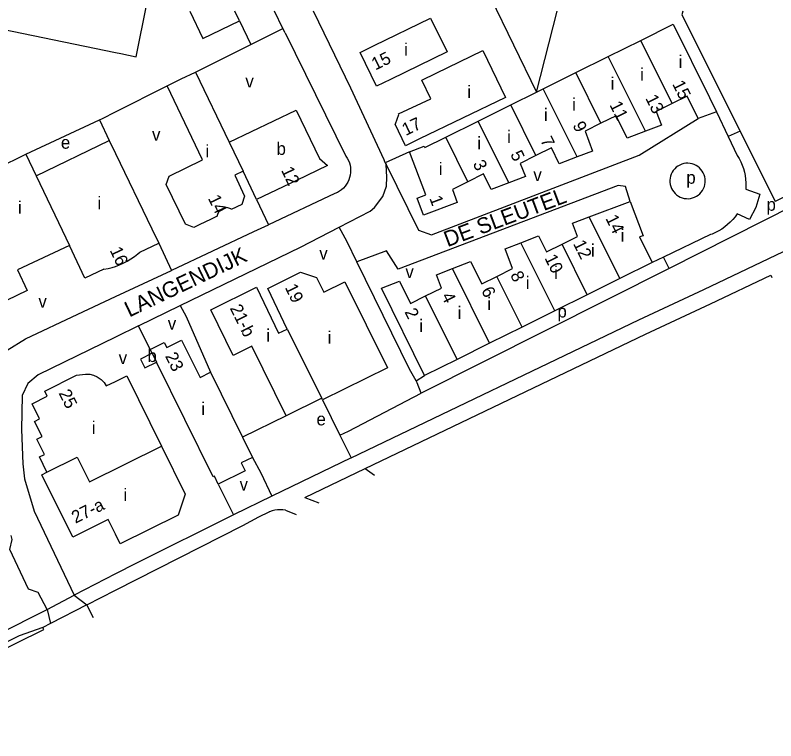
# Model space of a CAD drawing. Extents: x 157699 to 159683, y 381451 to 383293.
# Drawn here: x 158018.2 to 158260, y 381518.2 to 381748.7 of the extents above; entities that cross this region are included whole.
import ezdxf

# ---------------------------------------------------------------- set-up
doc = ezdxf.new("R2010")
doc.units = 0
for name, color, linetype in [('BLT_Basislijn', 7, 'Continuous'), ('BLT_Bebouwing', 7, 'Continuous'), ('BLT_Centroide', 7, 'Continuous'), ('BLT_Huisnummer', 7, 'Continuous'), ('BLT_Huisnummer_ tussenligend', 7, 'Continuous'), ('BLT_Huisnummer_reeks', 7, 'Continuous'), ('BLT_Onderverdeling_panden', 7, 'Continuous'), ('BLT_Straatnaam', 7, 'Continuous')]:
    doc.layers.add(name, color=color, linetype=linetype)

msp = doc.modelspace()

# ---------------------------------------------------------------- linework, layer by layer
at = {"layer": 'BLT_Basislijn'}
for p, q in [((158167.81, 381757.42), (158183.84, 381724.24)), ((158103.23, 381744.54), (158100.56, 381750)), ((158183.84, 381724.24), (158190.41, 381750)), ((158089.49, 381746.92), (158093.05, 381739.46)), ((158093.05, 381739.46), (158103.23, 381744.54)), ((158103.94, 381743.1), (158103.23, 381744.54)), ((158103.94, 381743.1), (158123.3, 381703.95)), ((158075.43, 381730.66), (158093.05, 381739.46)), ((158050, 381717.98), (158066.42, 381726.3)), ((158241.14, 381718.07), (158244.87, 381710.14)), ((158021.49, 381704.53), (158044.98, 381715.47)), ((158044.98, 381715.47), (158048.02, 381708.92)), ((158315.83, 381713.68), (158226.02, 381668.19)), ((158248.59, 381711.93), (158244.87, 381710.14)), ((158244.87, 381710.14), (158247.68, 381704.16)), ((158143.48, 381705.35), (158135.8, 381701.79)), ((158135.8, 381701.79), (158136.06, 381701.27)), ((158119.78, 381692.03), (158098.65, 381682.14)), ((158094.92, 381690.12), (158098.65, 381682.14)), ((158239.16, 381678.99), (158224.27, 381671.88)), ((158063.79, 381676.31), (158067.82, 381667.64)), ((158224.27, 381671.88), (158220.69, 381670.15)), ((158226.02, 381668.19), (158224.27, 381671.88)), ((158050, 381659.32), (158067.82, 381667.64)), ((158226.02, 381668.19), (158147.23, 381628.64)), ((158239.25, 381657.03), (158258.38, 381666.16)), ((158258.38, 381666.16), (158258.75, 381665.39)), ((158057.32, 381650.02), (158070.61, 381656.49)), ((158057.32, 381650.02), (158050, 381646.44)), ((158061.07, 381642.53), (158057.32, 381650.02)), ((158145.59, 381632.5), (158148.31, 381634.22)), ((158115.88, 381626.52), (158121.4, 381615.3)), ((158104.27, 381621.43), (158090.45, 381614.62)), ((158121.4, 381615.3), (158124.96, 381608.09)), ((158093.61, 381608.23), (158096.23, 381603.34)), ((158124.96, 381608.09), (158099.76, 381595.91)), ((158110.21, 381595.49), (158129.38, 381604.66)), ((158096.23, 381603.34), (158099.76, 381595.91)), ((158082.69, 381599.75), (158087.61, 381589.91)), ((158099.76, 381595.91), (158087.61, 381589.91)), ((158110.21, 381595.49), (158114.68, 381593.72)), ((158095.57, 381589.28), (158098.89, 381590.86)), ((158050, 381571.17), (158036.94, 381564.44)), ((158040.88, 381561.38), (158050, 381566.01)), ((158028.36, 381559.84), (158036.94, 381564.44)), ((158036.94, 381564.44), (158040.88, 381561.38)), ((157952.35, 381521.92), (158028.36, 381559.84)), ((158028.36, 381559.84), (158029.42, 381555.45))]:
    msp.add_line(p, q, dxfattribs=at)
for points in [[(158135.8, 381701.79), (158135.43, 381702.75), (158124.84, 381725.53), (158113.04, 381750)], [(158044.98, 381715.47), (158045.91, 381715.91), (158050, 381717.98)], [(158136.06, 381701.27), (158146.36, 381680.4), (158150.5, 381678.91), (158216.51, 381704.23), (158235.32, 381715.92)], [(158237.13, 381661.56), (158335.95, 381708.7)], [(158123.3, 381703.95), (158123.73, 381703.29), (158124.1, 381702.58), (158124.39, 381701.85), (158124.6, 381701.08), (158124.74, 381700.3), (158124.79, 381699.51), (158124.77, 381698.72), (158124.67, 381697.93), (158124.49, 381697.16), (158124.23, 381696.42), (158123.89, 381695.7), (158123.49, 381695.02), (158123.02, 381694.38), (158122.49, 381693.79), (158121.9, 381693.26), (158121.26, 381692.79), (158120.58, 381692.39), (158119.78, 381692.03)], [(158247.68, 381704.16), (158248.28, 381703.17), (158248.82, 381702.15), (158249.28, 381701.08), (158249.67, 381699.99), (158249.99, 381698.87), (158250.22, 381697.74), (158250.38, 381696.59), (158250.46, 381695.43), (158250.45, 381694.27), (158250.4, 381693.45)], [(158121.11, 381681.34), (158131.01, 381686.47), (158132.34, 381687.59), (158135.05, 381691.09), (158136.16, 381694.43), (158136.29, 381697.29), (158136.06, 381701.27)], [(158237.55, 381696.05), (158237.51, 381696.72), (158237.39, 381697.38), (158237.19, 381698.02), (158236.92, 381698.64), (158236.58, 381699.22), (158236.17, 381699.75), (158235.7, 381700.23), (158235.18, 381700.65), (158234.61, 381701), (158234, 381701.29), (158233.36, 381701.5), (158232.71, 381701.63), (158232.04, 381701.69), (158231.37, 381701.66), (158230.7, 381701.56), (158230.06, 381701.38), (158229.44, 381701.12), (158228.85, 381700.79), (158228.31, 381700.39), (158227.82, 381699.93), (158227.39, 381699.42), (158227.02, 381698.86), (158226.72, 381698.26), (158226.5, 381697.62), (158226.35, 381696.97), (158226.28, 381696.3), (158226.29, 381695.63), (158226.38, 381694.96), (158226.55, 381694.31), (158226.79, 381693.69), (158227.11, 381693.1), (158227.5, 381692.55), (158227.94, 381692.05), (158228.45, 381691.6), (158229, 381691.22), (158229.6, 381690.91), (158230.22, 381690.67), (158230.87, 381690.51), (158231.54, 381690.43), (158232.21, 381690.42), (158232.88, 381690.5), (158233.53, 381690.65), (158234.16, 381690.88), (158234.76, 381691.19), (158235.32, 381691.56), (158235.83, 381692), (158236.28, 381692.49), (158236.68, 381693.04), (158237, 381693.62), (158237.25, 381694.25), (158237.43, 381694.89), (158237.53, 381695.56), (158237.55, 381696.05)], [(158213.69, 381689.55), (158212.21, 381694.3), (158209.89, 381694.63), (158139.91, 381667.98), (158136.2, 381673.83), (158126.8, 381670.38)], [(158250.4, 381693.45), (158254.87, 381691.85), (158253.61, 381687.61), (158251.62, 381683.78), (158247.7, 381685.65)], [(158247.7, 381685.65), (158247.03, 381684.7), (158246.3, 381683.81), (158245.51, 381682.96), (158244.65, 381682.17), (158243.75, 381681.44), (158242.8, 381680.78), (158241.81, 381680.18), (158240.77, 381679.65), (158239.71, 381679.2), (158239.16, 381678.99)], [(158067.82, 381667.64), (158068, 381667.72), (158093.98, 381679.96), (158098.65, 381682.14)], [(158070.61, 381656.49), (158108.83, 381675.05), (158121.11, 381681.34)], [(158126.8, 381670.38), (158123.71, 381676.69), (158121.11, 381681.34)], [(158145.59, 381632.5), (158143.51, 381636.23), (158126.8, 381670.38)], [(158124.96, 381608.09), (158216.4, 381651.88), (158237.13, 381661.56)], [(158008.63, 381627.66), (158009.36, 381632.35), (158010.31, 381635.34), (158013.56, 381640.27), (158015.56, 381642.29), (158021.48, 381645.93), (158038.06, 381653.74), (158050, 381659.32)], [(158070.61, 381656.49), (158072.54, 381652.96), (158080.25, 381635.26)], [(158129.38, 381604.66), (158218.54, 381647.36), (158239.25, 381657.03)], [(158050, 381646.44), (158025.46, 381634.4), (158022.15, 381631.68), (158020.34, 381627.92), (158020.13, 381617.1), (158020.61, 381606.15), (158021.13, 381601.42), (158024.19, 381591.16), (158036.94, 381564.44)], [(158147.23, 381628.64), (158145.9, 381631.95), (158145.59, 381632.5)], [(158121.4, 381615.3), (158124.07, 381616.56), (158147.23, 381628.64)], [(158129.38, 381604.66), (158132.38, 381602.52)], [(158087.61, 381589.91), (158056.49, 381574.51), (158050, 381571.17)], [(158104.14, 381591.43), (158103.28, 381591.55), (158102.41, 381591.58), (158101.54, 381591.53), (158100.68, 381591.4), (158099.84, 381591.19), (158099.02, 381590.91), (158098.89, 381590.86)], [(158104.14, 381591.43), (158107.51, 381590.1)], [(158050, 381566.01), (158090.55, 381586.59), (158095.57, 381589.28)], [(158028.36, 381559.84), (158025.47, 381565.25), (158022.36, 381566.33), (158016.43, 381578.93), (158017.17, 381582.14), (158016.92, 381583.37)], [(158040.88, 381561.38), (158029.42, 381555.45)], [(158043.09, 381557.25), (158040.88, 381561.38)], [(158026.95, 381554.17), (158019.39, 381551.51), (157952.98, 381518.16)], [(158011.15, 381542.3), (158009.99, 381545.03), (158027.25, 381553.57), (158026.95, 381554.17)], [(158029.42, 381555.45), (158026.95, 381554.17)]]:
    msp.add_lwpolyline(points, dxfattribs=at)
at = {"layer": 'BLT_Bebouwing'}
for p, q in [((158206.71, 381735.6), (158217.04, 381740.73)), ((158196.38, 381730.47), (158206.71, 381735.6)), ((158075.43, 381730.66), (158086.15, 381708.38)), ((158186.04, 381725.34), (158196.38, 381730.47)), ((158077.72, 381702.79), (158066.42, 381726.3)), ((158183.84, 381724.24), (158186.04, 381725.34)), ((158175.71, 381720.21), (158183.84, 381724.24)), ((158165.38, 381715.07), (158175.71, 381720.21)), ((158241.14, 381718.07), (158235.32, 381715.92)), ((158155.05, 381709.94), (158165.38, 381715.07)), ((158024.77, 381697.68), (158048.02, 381708.92)), ((158048.02, 381708.92), (158050, 381704.83)), ((158002.5, 381695.32), (158021.49, 381704.53)), ((158021.49, 381704.53), (158024.77, 381697.68)), ((158090.59, 381699.15), (158087.96, 381697.89)), ((158094.92, 381690.12), (158090.59, 381699.15)), ((158200.63, 381684.61), (158213.69, 381689.55)), ((158057.76, 381673.42), (158063.79, 381676.31)), ((158220.69, 381670.15), (158210.35, 381665.02)), ((158210.35, 381665.02), (158200.01, 381659.89)), ((158200.01, 381659.89), (158189.67, 381654.75)), ((158189.67, 381654.75), (158179.33, 381649.62)), ((158179.33, 381649.62), (158168.99, 381644.49)), ((158168.99, 381644.49), (158158.65, 381639.35)), ((158158.65, 381639.35), (158148.31, 381634.22)), ((158080.25, 381635.26), (158090.45, 381614.62)), ((158090.45, 381614.62), (158093.61, 381608.23))]:
    msp.add_line(p, q, dxfattribs=at)
for points in [[(158050, 381736.86), (158051.69, 381736.51), (158056.59, 381735.5), (158060.04, 381752.38)], [(158008.27, 381750), (158007.37, 381745.62), (158050, 381736.86)], [(158073.63, 381750), (158077.8, 381741.31), (158089.49, 381746.92)], [(158089.49, 381746.92), (158088.01, 381750)], [(158230.44, 381750), (158230.14, 381748.88), (158248.59, 381711.93)], [(158155.45, 381737.08), (158137.48, 381728.32), (158132.98, 381726.13), (158127.8, 381736.93), (158132.3, 381739.12), (158150.22, 381747.84), (158155.45, 381737.08)], [(158217.04, 381740.73), (158227.36, 381745.86), (158238.88, 381722.63), (158241.14, 381718.07)], [(158151.95, 381730.3), (158166.88, 381737.5), (158174.05, 381722.62), (158146.72, 381709.45), (158142.19, 381707.27), (158138.91, 381714.09), (158139.08, 381714.18), (158140.12, 381717.15), (158140.03, 381717.35), (158150.29, 381722.17), (158147.45, 381728.13), (158151.95, 381730.3)], [(158066.42, 381726.3), (158070.93, 381728.48), (158075.43, 381730.66)], [(158235.32, 381715.92), (158231.82, 381722.99), (158227.03, 381720.62)], [(158227.03, 381720.62), (158221.96, 381718.11), (158223.61, 381713.82), (158218.5, 381711.86)], [(158086.15, 381708.38), (158107.5, 381718.59), (158114.94, 381703.21), (158117.43, 381700.92), (158107.55, 381696.18), (158094.92, 381690.12)], [(158218.5, 381711.86), (158212.73, 381709.67), (158209.2, 381716.77), (158204.37, 381714.37)], [(158314.09, 381716.71), (158259.76, 381689.57)], [(158204.37, 381714.37), (158199.31, 381711.86), (158201.72, 381705.56), (158196.8, 381703.69)], [(158248.59, 381711.93), (158259.76, 381689.57)], [(158143.48, 381705.35), (158148.16, 381707.11), (158148.39, 381706.64), (158155.05, 381709.94)], [(158196.8, 381703.69), (158191.07, 381701.51), (158188.63, 381706.54), (158183.71, 381704.1)], [(158050, 381704.83), (158061.62, 381680.81), (158063.79, 381676.31)], [(158162.1, 381695.83), (158157.15, 381693.36), (158158.7, 381689.25), (158147.96, 381685.18), (158145.92, 381690.57), (158148.71, 381691.63), (158143.48, 381705.35)], [(158183.71, 381704.1), (158178.73, 381701.64), (158180.35, 381697.47), (158175.12, 381695.47)], [(158087.96, 381697.89), (158091.1, 381691.27), (158090.17, 381688.61), (158086.82, 381687.02), (158086.72, 381687.2), (158085.45, 381687.64), (158082.78, 381686.29), (158082.32, 381685.05), (158082.39, 381684.9), (158080.47, 381683.95), (158076.61, 381682.11), (158074.97, 381681.31), (158072.26, 381682.33), (158066.2, 381694.95), (158067.14, 381697.61), (158077.72, 381702.79)], [(158175.12, 381695.47), (158169.51, 381693.32), (158167.05, 381698.3), (158162.1, 381695.83)], [(158213.69, 381689.55), (158217.81, 381678.65), (158216.65, 381678.29), (158220.69, 381670.15)], [(158192.02, 381675.99), (158196.9, 381678.41), (158195.3, 381682.6), (158200.63, 381684.61)], [(158178.91, 381676.42), (158184.56, 381678.57), (158187.06, 381673.53), (158192.02, 381675.99)], [(158035.42, 381675.59), (158018.85, 381667.83), (158021.94, 381661.24), (158008.55, 381654.76), (158005.46, 381661.15), (158004.2, 381660.58)], [(158046.34, 381667.99), (158040.31, 381665.16), (158035.42, 381675.59)], [(158171.33, 381665.73), (158176.31, 381668.2), (158173.91, 381674.52), (158178.91, 381676.42)], [(158050, 381668.92), (158051.27, 381669.4), (158052.52, 381669.95), (158053.73, 381670.58), (158054.9, 381671.28), (158056.03, 381672.04), (158057.11, 381672.87), (158057.76, 381673.42)], [(158157.2, 381668.23), (158162.95, 381670.42), (158166.47, 381663.32), (158171.33, 381665.73)], [(158046.34, 381667.99), (158047.68, 381668.25), (158049, 381668.6), (158050, 381668.92)], [(158148.65, 381659.5), (158153.69, 381662), (158152.07, 381666.27), (158157.2, 381668.23)], [(158104.65, 381649), (158098.44, 381661.87), (158108.91, 381667.11), (158113.95, 381665.33), (158116.3, 381660.71), (158123, 381664.03), (158136.52, 381636.69), (158115.88, 381626.52)], [(158148.31, 381634.22), (158134.57, 381661.98), (158140.31, 381664.26), (158143.85, 381657.12), (158148.65, 381659.5)], [(158104.27, 381621.43), (158093.39, 381643.51), (158087.49, 381640.61), (158080.35, 381655.06), (158094.86, 381662.26), (158101.9, 381647.68), (158104.65, 381649)], [(158061.07, 381642.53), (158065.51, 381644.72), (158066.32, 381643.1), (158071.05, 381645.45), (158076.91, 381633.62), (158080.25, 381635.26)], [(158061.69, 381641.28), (158057.99, 381639.46), (158059.37, 381636.67), (158063.04, 381638.49)], [(158061.69, 381641.28), (158061.07, 381642.53)], [(158082.69, 381599.75), (158081.47, 381602.22), (158081.08, 381602.03), (158063.04, 381638.49)], [(158028.25, 381603.51), (158025.86, 381608.35), (158027.47, 381609.15), (158025.07, 381614), (158026.68, 381614.8), (158024.28, 381619.64), (158025.9, 381620.44), (158023.5, 381625.27), (158028.34, 381627.67), (158027.54, 381629.28), (158037.69, 381634.3), (158040.53, 381634.66), (158041.93, 381634.62), (158043.09, 381634.32), (158044.24, 381633.84), (158045.46, 381633), (158046.39, 381631.99), (158047.05, 381630.9)], [(158050, 381632.36), (158053.62, 381634.15), (158064.67, 381611.77)], [(158047.05, 381630.9), (158050, 381632.36)], [(158115.62, 381627.03), (158104.27, 381621.43)], [(158115.88, 381626.52), (158115.62, 381627.03)], [(158064.67, 381611.77), (158072.18, 381596.56), (158069.93, 381589.9), (158051.49, 381580.76), (158050, 381583.77)], [(158093.61, 381608.23), (158090.03, 381606.46), (158091.23, 381603.97), (158082.69, 381599.75)], [(158050, 381583.77), (158047.67, 381588.48), (158036.47, 381582.88), (158026.64, 381602.71), (158028.25, 381603.51)]]:
    msp.add_lwpolyline(points, dxfattribs=at)
at = {"layer": 'BLT_Onderverdeling_panden'}
for p, q in [((158227.03, 381720.62), (158217.04, 381740.73)), ((158218.5, 381711.86), (158206.71, 381735.6)), ((158204.37, 381714.37), (158196.38, 381730.47)), ((158196.8, 381703.69), (158186.04, 381725.34)), ((158183.71, 381704.1), (158175.71, 381720.21)), ((158175.12, 381695.47), (158165.38, 381715.07)), ((158086.15, 381708.38), (158090.59, 381699.15)), ((158162.1, 381695.83), (158155.05, 381709.94)), ((158024.77, 381697.68), (158035.42, 381675.59)), ((158210.35, 381665.02), (158200.63, 381684.61)), ((158189.67, 381654.75), (158178.91, 381676.42)), ((158200.01, 381659.89), (158192.02, 381675.99)), ((158168.99, 381644.49), (158157.2, 381668.23)), ((158179.33, 381649.62), (158171.33, 381665.73)), ((158158.65, 381639.35), (158148.65, 381659.5)), ((158104.65, 381649), (158115.62, 381627.03)), ((158061.69, 381641.28), (158063.04, 381638.49))]:
    msp.add_line(p, q, dxfattribs=at)
msp.add_lwpolyline([(158028.25, 381603.51), (158037.87, 381608.27), (158041.75, 381600.43), (158064.67, 381611.77)], dxfattribs=at)

# ---------------------------------------------------------------- texts
at = {"layer": 'BLT_Centroide'}
for s, p in [('i', (158141.78, 381735.84)), ('i', (158229.09, 381732)), ('i', (158216.86, 381727.91)), ('v', (158091.34, 381725.77)), ('i', (158207.44, 381725.02)), ('i', (158161.88, 381722.38)), ('i', (158195.2, 381718.38)), ('i', (158186.25, 381715.14)), ('v', (158061.66, 381708.86)), ('i', (158174.55, 381708.12)), ('e', (158032.68, 381706.3)), ('b', (158101.24, 381704.34)), ('i', (158165.08, 381706.12)), ('i', (158078.66, 381703.53)), ('i', (158152.8, 381697.91)), ('v', (158182.89, 381696.02)), ('p', (158231.52, 381695.17)), ('i', (158019.03, 381685.62)), ('i', (158044.28, 381687.08)), ('p', (158257.02, 381686.59)), ('i', (158210.66, 381676.8)), ('i', (158201.19, 381671.98)), ('v', (158114.83, 381671.09)), ('v', (158142.21, 381665.22)), ('i', (158189.47, 381664.95)), ('i', (158180.5, 381661.7)), ('v', (158025.53, 381655.79)), ('i', (158168.27, 381655.08)), ('i', (158158.81, 381652.2)), ('p', (158190.55, 381652.66)), ('v', (158066.67, 381648.79)), ('i', (158146.61, 381648.08)), ('i', (158097.98, 381644.98)), ('i', (158117.48, 381644.31)), ('v', (158051.07, 381637.87)), ('b', (158060.19, 381638.52)), ('i', (158077.34, 381621.72)), ('e', (158113.94, 381618.39)), ('i', (158042.52, 381615.69)), ('v', (158089.49, 381597.68)), ('i', (158052.6, 381594.31))]:
    msp.add_text(s, height=4, dxfattribs=at).set_placement(p)
at = {"layer": 'BLT_Huisnummer'}
for s, rotation, p in [('15', 25.9707, (158132.65, 381731.14)), ('15', 296.4133, (158226.95, 381726.88)), ('17', 25.713, (158142.32, 381710.33)), ('9', 296.4135, (158195.28, 381713.8)), ('5', 296.4141, (158175.46, 381704.55)), ('12', 295.6276, (158102.61, 381699.5)), ('14', 295.4501, (158079.37, 381690.56)), ('1', 290.7495, (158149.77, 381690.57)), ('14', 296.3998, (158205.74, 381684.19)), ('16', 295.0947, (158048.13, 381674.08)), ('10', 296.4009, (158186.35, 381671.59)), ('19', 295.7631, (158103.81, 381662.25)), ('6', 296.4007, (158166.23, 381661.28)), ('2', 296.3334, (158141.86, 381654.46)), ('23', 296.3302, (158065.71, 381640.45)), ('25', 296.3276, (158031.88, 381628.65))]:
    msp.add_text(s, height=4, rotation=rotation, dxfattribs=at).set_placement(p)
at = {"layer": 'BLT_Huisnummer_ tussenligend'}
for s, rotation, p in [('13', 296.4142, (158218.4, 381722.36)), ('11', 296.4153, (158207.02, 381720.28)), ('7', 296.414, (158184.99, 381708.99)), ('3', 296.5423, (158163.55, 381701.56)), ('12', 296.3998, (158195.46, 381676.13)), ('8', 296.4012, (158175.45, 381666.22)), ('4', 296.3999, (158153.55, 381659.51))]:
    msp.add_text(s, height=4, rotation=rotation, dxfattribs=at).set_placement(p)
at = {"layer": 'BLT_Huisnummer_reeks'}
for s, rotation, p in [('21-b', 296.2853, (158086.3, 381655.67)), ('27-a', 26.3371, (158037.3, 381587.1))]:
    msp.add_text(s, height=4, rotation=rotation, dxfattribs=at).set_placement(p)
at = {"layer": 'BLT_Straatnaam'}
for s, rotation, p in [('DE SLEUTEL', 20.578, (158155.58, 381674.99)), ('LANGENDIJK', 25.5025, (158054.43, 381652.65))]:
    msp.add_text(s, height=5, rotation=rotation, dxfattribs=at).set_placement(p)

doc.saveas('drawing.dxf')
